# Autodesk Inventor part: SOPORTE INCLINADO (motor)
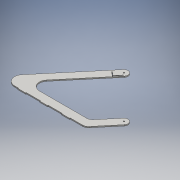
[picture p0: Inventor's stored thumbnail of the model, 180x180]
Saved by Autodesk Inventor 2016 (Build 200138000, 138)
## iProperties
Created: 2016-06
Part Number: SOPORTE INCLINADO (motor)
Material: Genérico
Document SubType Name: Modeling
Designer: adm
Density: 1 g/cm^3
Appearance: Valor por defecto
Author: adm
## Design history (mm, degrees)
sketch "Boceto1"
  geometry: L1 (75.83, -250.705)-(156.742, -154.277); L2 (57.177, -210.705)-(126.1, -128.566); L3 (34.196, -221.421)-(-203.95, -221.421); L4 (-54.102, 59.39)-(-234.592, -155.71); L5 (-86.032, 83.566)-(-320.372, -195.71); L6 (-269.73, -261.421)-(-269.73, -264.421); L7 (-229.73, -261.421)-(-229.73, -264.421); L8 (-159.73, -261.421)-(-159.73, -264.421); L9 (-119.73, -261.421)-(-119.73, -264.421); L10 (-49.73, -261.421)-(-49.73, -264.421); L11 (-9.73, -261.421)-(-9.73, -264.421); L12 (-49.73, -264.421)-(-9.73, -264.421); L13 (-269.73, -264.421)-(-229.73, -264.421); L14 (-159.73, -264.421)-(-119.73, -264.421); L15 (52.848, -261.421)-(-9.73, -261.421); L16 (-49.73, -261.421)-(-119.73, -261.421); L17 (-159.73, -261.421)-(-229.73, -261.421); L18 (-269.73, -261.421)-(-289.73, -261.421); C1 r 3.25 at (141.421, -141.421); C2 r 3.25 at (-70.711, 70.711); A1 r 30 centre (52.848, -231.421) between (52.848, -261.421) and (75.83, -250.705); A2 r 20 centre (141.421, -141.421) between (156.742, -154.277) and (126.1, -128.566); A3 r 30 centre (34.196, -191.421) between (34.196, -221.421) and (57.177, -210.705); A4 r 20.1 centre (-70.711, 70.711) between (-56.678, 56.32) and (-87.319, 82.032); A5 r 40 centre (-203.95, -181.421) between (-234.592, -155.71) and (-203.95, -221.421); A6 r 40 centre (-289.73, -221.421) between (-320.372, -195.71) and (-289.73, -261.421); 3 further points
  constraints: 36 end point, 15 tangent, 13 point on circle, 8 centre point, 2 coincident, 2 point on line
  dimensions: "d3" = 40 radius of A6; "d5" = 40 radius of A5; "d6" = 30 radius of A3; "d7" = 30 radius of A1; "d20" = 6.5 diameter of C2; "d21" = 6.5 diameter of C1
extrude "Extrusión1" new body sketch "Boceto1" distance "d18" = 6; taper "d19" = 0 deg
sketch "Boceto2"
  geometry: 1 further point
extrude "Extrusión2" cut sketch "Boceto2" distance "d36" = 10; taper "d37" = 0 deg
sketch "Boceto3"
  geometry: L1 (104.083, 46.497)-(88.762, 33.641); L2 (106.14, 44.045)-(90.819, 31.19); L3 (104.083, 46.497)-(106.14, 44.045); L4 (88.762, 33.641)-(90.819, 31.19); L5 (62.809, 59.903)-(88.521, 29.261); L6 (60.358, 57.846)-(86.069, 27.204); L7 (62.809, 59.903)-(60.358, 57.846); L8 (98.479, 37.618)-(90.819, 31.19); L9 (88.521, 29.261)-(86.069, 27.204); 3 further points
  constraints: 18 end point, 4 parallel, 1 coincident, 1 midpoint
  dimensions: "d50" = 3.2 distance between parallel lines of L1 L2; "d51" = 3.2 distance between parallel lines of L5 L6
extrude "Extrusión3" cut sketch "Boceto3" distance "d52" = 10; taper "d53" = 0 deg
node "Sólido1"
other parameters: "d4" = 50 deg, "d11" = 3, "d23" = 3, "d33" = 3, "d34" = 2
